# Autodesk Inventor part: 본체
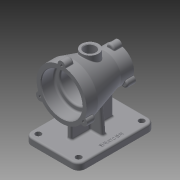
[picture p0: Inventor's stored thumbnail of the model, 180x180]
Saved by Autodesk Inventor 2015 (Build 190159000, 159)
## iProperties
Created: 2020-03
Part Number: 본체
Material: 일반
Document SubType Name: Modeling
Designer: Administrator
Density: 1 g/cm^3
Appearance: 기본값
Mass: 370.18 g
Surface Area: 863.437 cm^2
Volume: 370.18 cm^3
Author: Administrator
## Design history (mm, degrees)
sketch "스케치1"
  geometry: L1 (47.5, -67.5)-(-47.5, -67.5); L2 (-47.5, -67.5)-(-47.5, 67.5); L3 (-47.5, 67.5)-(47.5, 67.5); L4 (47.5, 67.5)-(47.5, -67.5); L5 (47.5, -67.5)-(-47.5, 67.5); L6 (-47.5, -67.5)-(47.5, 67.5); 1 further point
  constraints: 12 end point, 2 midpoint, 2 parallel, 1 horizontal, 1 perpendicular
  dimensions: "d0" = 95 distance of L2.end L3.end; "d1" = 135 distance of L1.end L2.end
extrude "돌출1" new body sketch "스케치1" distance "d2" = 12; taper "d3" = 0 deg
fillet "모깎기1" dims "d4" = 12
sketch "스케치2"
  geometry: L1 (-47.5, 55.5)-(-47.5, -55.5) reference; L2 (-35.5, -67.5)-(35.5, -67.5) reference; L3 (47.5, -55.5)-(47.5, 55.5) reference; L4 (35.5, 67.5)-(-35.5, 67.5) reference; A1 r 12 centre (-35.5, 55.5) between (-35.5, 67.5) and (-47.5, 55.5) reference; A2 r 12 centre (-35.5, -55.5) between (-47.5, -55.5) and (-35.5, -67.5) reference; A3 r 12 centre (35.5, -55.5) between (35.5, -67.5) and (47.5, -55.5) reference; A4 r 12 centre (35.5, 55.5) between (47.5, 55.5) and (35.5, 67.5) reference; 5 further points
  constraints: 4 coincident
hole "구멍1" sketch "스케치2" at (-35.5, -55.5), (35.5, -55.5), (-35.5, 55.5), (35.5, 55.5) diameter "d5" = 10; stored, may be unused: countersink angle "d9" = 90 deg, drill point angle "d11" = 118 deg; dims "d6" = 6, "d7" = 4, "d8" = 2, "d10" = 8
sketch "스케치3"
  geometry: L1 (0, 0)-(0, 12); L2 (0, 12)-(25, 12); L3 (25, 12)-(18.439, 86.997); L4 (18.439, 86.997)-(-18.439, 86.997) reference; L5 (0, 12)-(-25, 12); L6 (-25, 12)-(-18.439, 86.997)
  constraints: 12 end point, 2 horizontal, 1 parallel, 1 perpendicular, 1 vertical
  dimensions: "d12" = 12 distance of L1.start L1.end; "d13" = 25 distance of L1.end L2.end; "d14" = 85 deg angle of L3 L2; "d15" = 25 distance of L1.end L5.end; "d16" = 85 deg angle of L5 L6
extrude "돌출2" join sketch "스케치3" stored distance "d17" = 8; taper "d18" = 0 deg
sketch "스케치4"
  geometry: L1 (-4, -37)-(4, -37); L2 (4, -37)-(4, 37); L3 (4, 37)-(-4, 37); L4 (-4, 37)-(-4, -37); L5 (-4, -37)-(4, 37); L6 (4, -37)-(-4, 37); 1 further point
  constraints: 12 end point, 2 midpoint, 2 parallel, 1 horizontal, 1 perpendicular
  dimensions: "d19" = 8 distance of L3.end L2.end; "d20" = 74 distance of L2.end L1.end
extrude "돌출3" join sketch "스케치4" distance "d21" = 78; taper "d22" = 0 deg
sketch "스케치5"
  geometry: L1 (0, 0)-(87, 0); L2 (86.997, 50)-(86.997, -50); L3 (86.997, -4)-(86.997, 4) reference; L4 (86.997, 50)-(130.997, 50); L5 (130.997, 50)-(130.997, 30); L6 (59.497, -50)-(114.497, -50); L7 (130.997, 30)-(114.497, -27); L8 (114.497, -50)-(114.497, -27); 1 further point
  constraints: 14 end point, 3 horizontal, 3 midpoint, 2 vertical, 1 perpendicular
  dimensions: "d23" = 87 distance of L1.start L1.end; "d24" = 100 distance of L2.end L2.start; "d25" = 44 distance of L2.start L4.end; "d26" = 20 distance of L4.end L5.end; "d68" = 55 distance of L6.start L6.end
revolve "회전1" sketch "스케치5" stored, may be unused: angle "d30" = 90 deg
sketch "스케치6"
  geometry: C1 r 7 at (0, 44); 2 further points
  constraints: 1 centre point, 1 vertical alignment, 1 other
  dimensions: "d31" = 7 radius of C1
extrude "돌출4" join sketch "스케치6" distance "d32" = 15; taper "d33" = 0 deg
sketch "스케치8"
  geometry: A1 r 44 centre (0, -44) between (-34.134, -71.765) and (34.134, -71.765) reference; A2 r 7 centre (38.105, -66) between (34.134, -71.765) and (41.112, -59.679) reference; A3 r 44 centre (0, -44) between (41.112, -59.679) and (6.978, -0.557) reference; A4 r 7 centre (0, 0) between (6.978, -0.557) and (-6.978, -0.557) reference; A5 r 44 centre (0, -44) between (-6.978, -0.557) and (-41.112, -59.679) reference; A6 r 7 centre (-38.105, -66) between (-41.112, -59.679) and (-34.134, -71.765) reference; 4 further points
  constraints: 3 coincident
hole "구멍2" sketch "스케치8" at (0, 0), (-38.105, -66), (38.105, -66) diameter "d43" = 4.134; stored, may be unused: countersink angle "d47" = 90 deg, drill point angle "d49" = 118 deg; dims "d44" = 9, "d45" = 4, "d46" = 2, "d48" = 11
fillet "모깎기2" dims "d57" = 3
fillet "모깎기3" dims "d58" = 1
node "작업 평면1"
sketch "스케치10"
  geometry: C1 r 15 at (0, 0); 1 further point
  constraints: 1 centre point, 1 coincident
  dimensions: "d60" = 30 diameter of C1
extrude "돌출6" join sketch "스케치10" stored distance "d61" = 15; taper "d62" = 0 deg
sketch "스케치11"
  geometry: C1 r 2.067 at (-38.105, -66) reference; C2 r 2.067 at (0, 0) reference; C3 r 2.067 at (38.105, -66) reference; C4 r 36 at (0, -44); A1 r 1 centre (34.354, -73.066) between (34.823, -72.183) and (33.59, -72.42) reference; A2 r 7 centre (38.105, -66) between (34.823, -72.183) and (41.818, -60.066) reference; A3 r 1 centre (42.349, -59.218) between (41.408, -58.88) and (41.818, -60.066) reference; A4 r 44 centre (0, -44) between (41.408, -58.88) and (7.817, -0.7) reference; A5 r 1 centre (7.995, 0.284) between (6.996, 0.249) and (7.817, -0.7) reference; A6 r 7 centre (0, 0) between (6.996, 0.249) and (-6.996, 0.249) reference; A7 r 1 centre (-7.995, 0.284) between (-7.817, -0.7) and (-6.996, 0.249) reference; A8 r 44 centre (0, -44) between (-7.817, -0.7) and (-41.408, -58.88) reference; A9 r 1 centre (-42.349, -59.218) between (-41.818, -60.066) and (-41.408, -58.88) reference; A10 r 7 centre (-38.105, -66) between (-41.818, -60.066) and (-34.823, -72.183) reference; A11 r 1 centre (-34.354, -73.066) between (-33.59, -72.42) and (-34.823, -72.183) reference; A12 r 44 centre (0, -44) between (-33.59, -72.42) and (33.59, -72.42) reference; 1 further point
  constraints: 1 centre point, 1 coincident
  dimensions: "d64" = 72 diameter of C4
extrude "돌출7" cut sketch "스케치11" distance "d65" = 23; taper "d66" = 0 deg
sketch "스케치12"
  geometry: C1 r 36 at (0, 0) reference; C2 r 26 at (0, 0); 1 further point
  constraints: 1 centre point, 1 coincident
  dimensions: "d67" = 52 diameter of C2
extrude "돌출8" cut sketch "스케치12" distance "d70" = 47; taper "d71" = 0 deg
sketch "스케치13"
  geometry: C1 r 7 at (0, 27.5); 2 further points
  constraints: 1 centre point, 1 vertical alignment, 1 other
  dimensions: "d72" = 14 diameter of C1
extrude "돌출9" join sketch "스케치13" distance "d73" = 15; taper "d74" = 0 deg
sketch "스케치14"
  geometry: A1 r 27.5 centre (0, -27.5) between (26.516, -34.792) and (6.943, -0.891) reference; A2 r 7 centre (0, 0) between (6.943, -0.891) and (-6.943, -0.891) reference; A3 r 27.5 centre (0, -27.5) between (-6.943, -0.891) and (-26.516, -34.792) reference; A4 r 7 centre (-23.816, -41.25) between (-26.516, -34.792) and (-19.573, -46.817) reference; A5 r 27.5 centre (0, -27.5) between (-19.573, -46.817) and (19.573, -46.817) reference; A6 r 7 centre (23.816, -41.25) between (19.573, -46.817) and (26.516, -34.792) reference; 4 further points
  constraints: 3 coincident
hole "구멍4" sketch "스케치14" at (0, 0), (-23.816, -41.25), (23.816, -41.25) diameter "d78" = 4.134; stored, may be unused: countersink angle "d82" = 90 deg, drill point angle "d84" = 118 deg; dims "d79" = 9, "d80" = 4, "d81" = 2, "d83" = 11
fillet "모깎기5" dims "d85" = 3
fillet "모깎기6" dims "d86" = 1
sketch "스케치15"
  geometry: C1 r 26 at (0, 0) reference; C2 r 20 at (0, 0); 1 further point
  constraints: 1 centre point, 1 coincident
  dimensions: "d87" = 40 diameter of C2
extrude "돌출10" cut sketch "스케치15" distance "d88" = 30; taper "d89" = 0 deg
sketch "스케치16"
  geometry: C1 r 15 at (0, 0) reference; C2 r 10 at (0, 0); 1 further point
  constraints: 1 centre point, 1 coincident
  dimensions: "d90" = 20 diameter of C2
extrude "돌출11" cut sketch "스케치16" distance "d91" = 30; taper "d92" = 0 deg
fillet "모깎기7" dims "d93" = 3
chamfer "모따기1" distance "d94" = 1; stored, may be unused: second distance "d95" = 2, angle "d96" = 45 deg
fillet "모깎기8" dims "d97" = 3
fillet "모깎기9" dims "d98" = 3
fillet "모깎기10" dims "d99" = 3
fillet "모깎기11" dims "d100" = 3
fillet "모깎기12" dims "d101" = 1
fillet "모깎기13" dims "d102" = 3
sketch "스케치17"
  geometry: L1 (47.5, -55.5)-(47.5, 55.5) reference; L2 (47.5, 0)-(37.5, 0); 2 further points
  constraints: 2 end point, 1 coincident, 1 horizontal, 1 midpoint, 1 other
  dimensions: "d103" = 10 distance of L2.start L2.end
feature "엠보싱1" sketch "스케치17" dims "d78" = 4.134, "d98" = 3, "d100" = 3, "d104" = 0.5, "d105" = 0
fillet "모깎기14" dims "d106" = 3
node "솔리드1"
pattern_circular "원형 패턴1" dims angle "d35" = 360 deg
pattern_circular "원형 패턴3" dims angle "d76" = 360 deg
node "투영된 루프1"
node "투영된 루프2"
node "투영된 루프4"
node "투영된 루프6"
node "투영된 루프7"
node "투영된 루프8"
node "투영된 루프9"
node "투영된 루프10"
node "투영된 루프11"
other parameters: "d59" = 132
